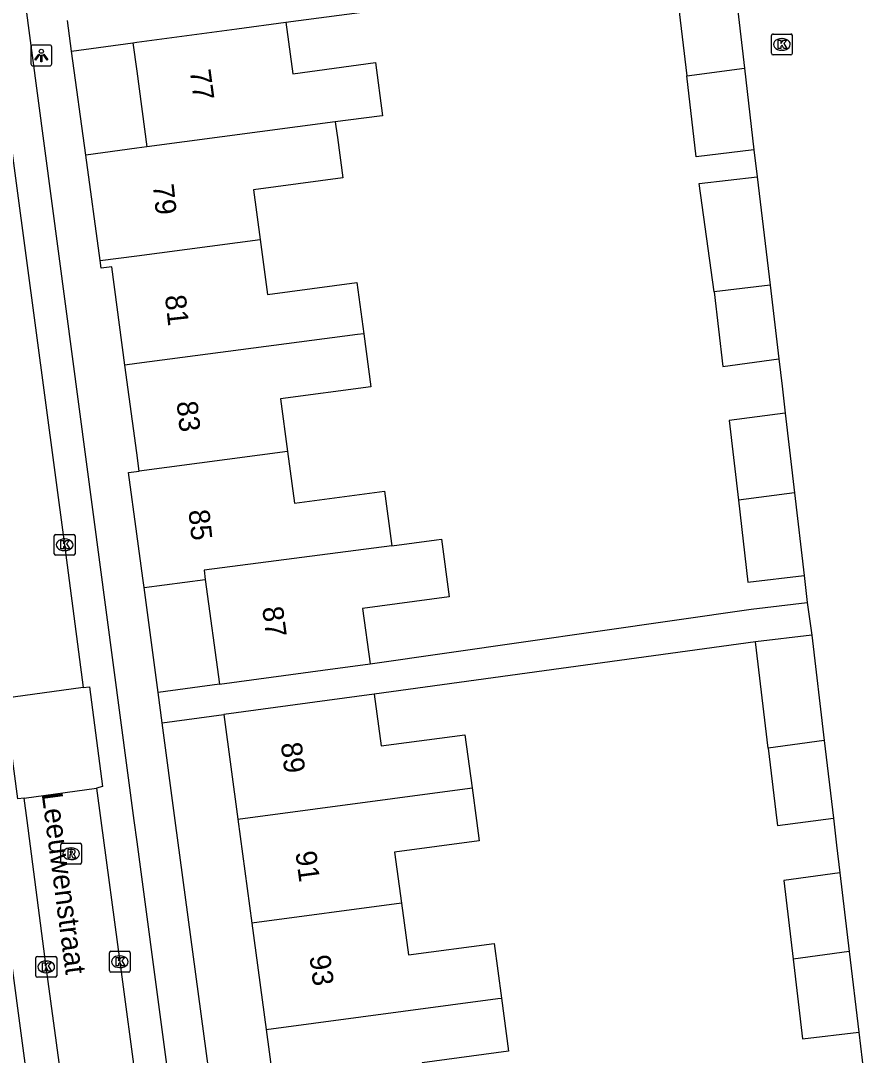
# Model space of a CAD drawing. Extents: x 163150 to 163546, y 380933 to 381635.
# Drawn here: x 163494.43 to 163535.32, y 381238.73 to 381288.37 of the extents above; entities that cross this region are included whole.
import ezdxf

# ---------------------------------------------------------------- set-up
doc = ezdxf.new("R2010")
doc.units = 0
for name, color, linetype in [('IMGEO_Kolk', 7, 'Continuous'), ('IMGEO_Lichtpunt', 7, 'Continuous'), ('IMGEO_Openbare_ruimte_label', 7, 'Continuous'), ('IMGEO_Pand', 7, 'Continuous'), ('IMGEO_Pand_nummerreeks', 7, 'Continuous'), ('IMGEO_Rijbaan_lokaal_open', 7, 'Continuous'), ('IMGEO_Rioolput', 7, 'Continuous'), ('IMGEO_Voetpad_open', 7, 'Continuous')]:
    doc.layers.add(name, color=color, linetype=linetype)

msp = doc.modelspace()

# ---------------------------------------------------------------- linework, layer by layer
at = {"layer": 'IMGEO_Kolk'}
for p, q in [((163530.439, 381286.802), (163530.439, 381287.654)), ((163530.514, 381287.728), (163531.366, 381287.728)), ((163530.927, 381287.508), (163530.952, 381287.508)), ((163531.44, 381287.654), (163531.44, 381286.802)), ((163530.95, 381286.948), (163530.925, 381286.948)), ((163531.366, 381286.728), (163530.514, 381286.728)), ((163496.041, 381262.797), (163496.041, 381263.649)), ((163496.116, 381263.723), (163496.968, 381263.723)), ((163496.529, 381263.503), (163496.554, 381263.503)), ((163497.042, 381263.649), (163497.042, 381262.797)), ((163496.552, 381262.943), (163496.527, 381262.943)), ((163496.968, 381262.723), (163496.116, 381262.723)), ((163498.686, 381242.797), (163498.686, 381243.649)), ((163498.761, 381243.723), (163499.613, 381243.723)), ((163499.687, 381243.649), (163499.687, 381242.797)), ((163495.16, 381242.55), (163495.16, 381243.402)), ((163495.235, 381243.476), (163496.087, 381243.476)), ((163495.648, 381243.256), (163495.673, 381243.256)), ((163496.161, 381243.402), (163496.161, 381242.55)), ((163499.174, 381243.503), (163499.199, 381243.503)), ((163495.671, 381242.696), (163495.646, 381242.696)), ((163499.613, 381242.723), (163498.761, 381242.723)), ((163499.197, 381242.943), (163499.172, 381242.943)), ((163496.087, 381242.476), (163495.235, 381242.476))]:
    msp.add_line(p, q, dxfattribs=at)
for points in [[(163530.439, 381286.802), (163530.439, 381287.654)], [(163530.514, 381287.728), (163531.366, 381287.728)], [(163530.76, 381287.428), (163530.883, 381287.428), (163530.883, 381287.277), (163531.013, 381287.428), (163531.177, 381287.428), (163531.031, 381287.277), (163531.184, 381287.028), (163531.032, 381287.028), (163530.947, 381287.192), (163530.883, 381287.125), (163530.883, 381287.028), (163530.76, 381287.028), (163530.76, 381287.428)], [(163531.44, 381287.654), (163531.44, 381286.802)], [(163531.366, 381286.728), (163530.514, 381286.728)], [(163496.041, 381262.797), (163496.041, 381263.649)], [(163496.116, 381263.723), (163496.968, 381263.723)], [(163497.042, 381263.649), (163497.042, 381262.797)], [(163496.362, 381263.423), (163496.485, 381263.423), (163496.485, 381263.272), (163496.615, 381263.423), (163496.779, 381263.423), (163496.633, 381263.272), (163496.786, 381263.023), (163496.634, 381263.023), (163496.549, 381263.187), (163496.485, 381263.12), (163496.485, 381263.023), (163496.362, 381263.023), (163496.362, 381263.423)], [(163496.968, 381262.723), (163496.116, 381262.723)], [(163498.686, 381242.797), (163498.686, 381243.649)], [(163498.761, 381243.723), (163499.613, 381243.723)], [(163499.687, 381243.649), (163499.687, 381242.797)], [(163495.16, 381242.55), (163495.16, 381243.402)], [(163495.235, 381243.476), (163496.087, 381243.476)], [(163495.481, 381243.176), (163495.604, 381243.176), (163495.604, 381243.025), (163495.734, 381243.176), (163495.898, 381243.176), (163495.752, 381243.025), (163495.905, 381242.776), (163495.753, 381242.776), (163495.668, 381242.94), (163495.604, 381242.873), (163495.604, 381242.776), (163495.481, 381242.776), (163495.481, 381243.176)], [(163496.161, 381243.402), (163496.161, 381242.55)], [(163499.007, 381243.423), (163499.13, 381243.423), (163499.13, 381243.272), (163499.26, 381243.423), (163499.424, 381243.423), (163499.278, 381243.272), (163499.431, 381243.023), (163499.279, 381243.023), (163499.194, 381243.187), (163499.13, 381243.12), (163499.13, 381243.023), (163499.007, 381243.023), (163499.007, 381243.423)], [(163499.613, 381242.723), (163498.761, 381242.723)], [(163496.087, 381242.476), (163495.235, 381242.476)]]:
    msp.add_lwpolyline(points, dxfattribs=at)
for centre, start, end in [((163530.516, 381287.652), 91.552, 178.448), ((163530.516, 381287.652), 91.552, 178.448), ((163531.364, 381287.652), 1.552, 88.448), ((163531.364, 381287.652), 1.552, 88.448), ((163530.516, 381286.804), 181.552, 268.448), ((163530.516, 381286.804), 181.552, 268.448), ((163531.364, 381286.804), 271.552, 358.448), ((163531.364, 381286.804), 271.552, 358.448), ((163496.118, 381263.647), 91.552, 178.448), ((163496.118, 381263.647), 91.552, 178.448), ((163496.966, 381263.647), 1.552, 88.448), ((163496.966, 381263.647), 1.552, 88.448), ((163496.118, 381262.799), 181.552, 268.448), ((163496.118, 381262.799), 181.552, 268.448), ((163496.966, 381262.799), 271.552, 358.448), ((163496.966, 381262.799), 271.552, 358.448), ((163498.763, 381243.647), 91.552, 178.448), ((163498.763, 381243.647), 91.552, 178.448), ((163499.611, 381243.647), 1.552, 88.448), ((163499.611, 381243.647), 1.552, 88.448), ((163495.237, 381243.4), 91.552, 178.448), ((163495.237, 381243.4), 91.552, 178.448), ((163496.085, 381243.4), 1.552, 88.448), ((163496.085, 381243.4), 1.552, 88.448), ((163498.763, 381242.799), 181.552, 268.448), ((163498.763, 381242.799), 181.552, 268.448), ((163499.611, 381242.799), 271.552, 358.448), ((163499.611, 381242.799), 271.552, 358.448), ((163495.237, 381242.552), 181.552, 268.448), ((163495.237, 381242.552), 181.552, 268.448), ((163496.085, 381242.552), 271.552, 358.448), ((163496.085, 381242.552), 271.552, 358.448)]:
    msp.add_arc(centre, 0.0765, start, end, dxfattribs=at)
for centre, major_axis, ratio, start_param, end_param in [((163530.926, 381287.228), (-0.387, 0.002), 0.722429, 4.712389, 7.853982), ((163530.951, 381287.228), (-0.39, 0.002), 0.717154, 1.570796, 4.712389), ((163496.528, 381263.223), (-0.387, 0.002), 0.722429, 4.712389, 7.853982), ((163496.553, 381263.223), (-0.39, 0.002), 0.717154, 1.570796, 4.712389), ((163495.647, 381242.976), (-0.387, 0.002), 0.722429, 4.712389, 7.853982), ((163495.672, 381242.976), (-0.39, 0.002), 0.717154, 1.570796, 4.712389), ((163499.173, 381243.223), (-0.387, 0.002), 0.722429, 4.712389, 7.853982), ((163499.198, 381243.223), (-0.39, 0.002), 0.717154, 1.570796, 4.712389)]:
    msp.add_ellipse(centre, major_axis=major_axis, ratio=ratio, start_param=start_param, end_param=end_param, dxfattribs=at)
at = {"layer": 'IMGEO_Lichtpunt'}
for p, q in [((163494.925, 381287.103), (163494.925, 381286.296)), ((163494.925, 381287.103), (163494.925, 381286.296)), ((163495.827, 381287.198), (163495.019, 381287.198)), ((163495.827, 381287.198), (163495.019, 381287.198)), ((163495.921, 381286.296), (163495.921, 381287.103)), ((163495.921, 381286.296), (163495.921, 381287.103)), ((163495.019, 381286.202), (163495.827, 381286.202)), ((163495.019, 381286.202), (163495.827, 381286.202))]:
    msp.add_line(p, q, dxfattribs=at)
for points in [[(163495.299, 381286.767), (163495.338, 381286.739), (163495.15, 381286.477), (163495.112, 381286.504), (163495.299, 381286.767)], [(163495.511, 381286.739), (163495.549, 381286.766), (163495.736, 381286.504), (163495.697, 381286.476), (163495.511, 381286.739)], [(163495.401, 381286.719), (163495.448, 381286.719), (163495.448, 381286.397), (163495.401, 381286.397), (163495.401, 381286.719)]]:
    msp.add_lwpolyline(points, dxfattribs=at)
msp.add_circle((163495.424, 381286.901), 0.0994, dxfattribs=at)
for centre, start, end in [((163495.019, 381287.103), 90, 180), ((163495.019, 381287.103), 90, 180), ((163495.827, 381287.103), 0, 90), ((163495.827, 381287.103), 0, 90), ((163495.019, 381286.296), 180, 270), ((163495.019, 381286.296), 180, 270), ((163495.827, 381286.296), 270, 0), ((163495.827, 381286.296), 270, 360)]:
    msp.add_arc(centre, 0.0946, start, end, dxfattribs=at)
at = {"layer": 'IMGEO_Pand'}
for points in [[(163528.71, 381289.796), (163525.939, 381289.473), (163526.375, 381285.729)], [(163528.71, 381289.796), (163529.141, 381286.094)], [(163499.816, 381287.309), (163500, 381287.334), (163504.795, 381287.979), (163507.155, 381288.296)], [(163507.155, 381288.296), (163507.488, 381285.823), (163511.447, 381286.355), (163511.791, 381283.807), (163511.644, 381283.788), (163509.523, 381283.509)], [(163499.816, 381287.309), (163500, 381285.942), (163500.488, 381282.318)], [(163526.375, 381285.729), (163529.141, 381286.094)], [(163529.141, 381286.094), (163529.6, 381282.164)], [(163529.6, 381282.164), (163526.829, 381281.841), (163526.375, 381285.729)], [(163509.523, 381283.509), (163500.488, 381282.318)], [(163509.523, 381283.509), (163509.552, 381283.291), (163509.624, 381282.757), (163509.884, 381280.823), (163505.601, 381280.247), (163505.921, 381277.867)], [(163500.488, 381282.318), (163500, 381282.252), (163497.556, 381281.923)], [(163498.238, 381276.858), (163497.556, 381281.923)], [(163527.686, 381275.36), (163526.979, 381280.551), (163529.75, 381280.874)], [(163529.75, 381280.874), (163530.382, 381275.674)], [(163498.238, 381276.858), (163500, 381277.09), (163505.921, 381277.867)], [(163505.921, 381277.867), (163506.276, 381275.229), (163510.556, 381275.805), (163510.887, 381273.347)], [(163499.434, 381271.845), (163498.8, 381276.56), (163498.287, 381276.491), (163498.238, 381276.858)], [(163530.382, 381275.674), (163527.686, 381275.36)], [(163527.686, 381275.36), (163528.104, 381271.782), (163530.795, 381272.139)], [(163530.382, 381275.674), (163530.795, 381272.139)], [(163510.887, 381273.347), (163510.579, 381273.307), (163500, 381271.919), (163499.434, 381271.845)], [(163510.887, 381273.347), (163511.229, 381270.804), (163506.897, 381270.222), (163507.236, 381267.699)], [(163500.119, 381266.756), (163500, 381267.641), (163499.434, 381271.845)], [(163531.098, 381269.542), (163528.406, 381269.185), (163528.852, 381265.361)], [(163531.098, 381269.542), (163531.544, 381265.714)], [(163507.236, 381267.699), (163500.119, 381266.756)], [(163507.236, 381267.699), (163507.569, 381265.224), (163511.874, 381265.803), (163512.212, 381263.288), (163512.226, 381263.181)], [(163500.348, 381261.17), (163500.288, 381261.616), (163500, 381263.757), (163499.606, 381266.687), (163500.119, 381266.756)], [(163531.544, 381265.714), (163528.852, 381265.361)], [(163531.544, 381265.714), (163532.006, 381261.75)], [(163528.852, 381265.361), (163529.31, 381261.436), (163532.006, 381261.75)], [(163512.226, 381263.181), (163514.374, 381263.463), (163514.609, 381263.494), (163514.981, 381260.734), (163510.829, 381260.175), (163511.187, 381257.513)], [(163512.226, 381263.181), (163503.227, 381262.001), (163503.286, 381261.566)], [(163500.348, 381261.17), (163503.286, 381261.566)], [(163503.286, 381261.566), (163503.962, 381256.541)], [(163532.376, 381258.889), (163529.68, 381258.575)], [(163530.283, 381253.469), (163529.68, 381258.575)], [(163532.376, 381258.889), (163532.973, 381253.829)], [(163503.962, 381256.541), (163508.918, 381257.208), (163511.187, 381257.513)], [(163511.38, 381256.054), (163509.13, 381255.751), (163504.174, 381255.085)], [(163511.38, 381256.054), (163511.714, 381253.572), (163515.739, 381254.113), (163516.081, 381251.569)], [(163504.174, 381255.085), (163504.849, 381250.067)], [(163532.973, 381253.829), (163530.283, 381253.469)], [(163532.973, 381253.829), (163533.411, 381250.117)], [(163530.283, 381253.469), (163530.692, 381250), (163530.721, 381249.757), (163533.411, 381250.117)], [(163504.849, 381250.067), (163515.966, 381251.554), (163516.081, 381251.569)], [(163516.081, 381251.569), (163516.292, 381250), (163516.423, 381249.026), (163512.367, 381248.481), (163512.697, 381246.027)], [(163504.849, 381250.067), (163505.522, 381245.067)], [(163533.722, 381247.486), (163531.031, 381247.126), (163531.477, 381243.35)], [(163533.722, 381247.486), (163534.168, 381243.71)], [(163512.697, 381246.027), (163505.522, 381245.067)], [(163512.697, 381246.027), (163513.03, 381243.549), (163517.135, 381244.101), (163517.488, 381241.478)], [(163505.522, 381245.067), (163506.207, 381239.968)], [(163534.168, 381243.71), (163531.477, 381243.35)], [(163534.168, 381243.71), (163534.624, 381239.844)], [(163531.477, 381243.35), (163531.928, 381239.53), (163534.624, 381239.844)], [(163506.207, 381239.968), (163517.317, 381241.455), (163517.488, 381241.478)], [(163517.488, 381241.478), (163517.83, 381238.933), (163513.69, 381238.376), (163514.021, 381235.914)], [(163506.207, 381239.968), (163506.881, 381234.959)]]:
    msp.add_lwpolyline(points, dxfattribs=at)
at = {"layer": 'IMGEO_Rijbaan_lokaal_open'}
for points in [[(163490.402, 381309.443), (163490.846, 381305.849), (163493.759, 381284.035), (163496.541, 381263.222), (163497.43, 381256.373)], [(163529.6, 381282.164), (163529.75, 381280.874)], [(163530.795, 381272.139), (163530.946, 381270.841), (163531.098, 381269.542)], [(163532.006, 381261.75), (163532.157, 381260.455)], [(163532.157, 381260.455), (163532.376, 381258.889)], [(163497.43, 381256.373), (163494.08, 381255.92)], [(163497.43, 381256.373), (163497.739, 381256.415), (163498.362, 381251.625), (163498.069, 381251.55)], [(163494.609, 381251.077), (163494.305, 381251.042), (163493.658, 381255.873), (163494.08, 381255.92)], [(163494.609, 381251.077), (163498.069, 381251.55)], [(163498.069, 381251.55), (163498.277, 381250), (163499.186, 381243.223), (163500, 381237.114), (163502.031, 381221.873), (163503.782, 381208.782)], [(163503.549, 381184.23), (163501.36, 381200.568), (163500, 381210.764), (163498.574, 381221.455), (163495.662, 381242.977), (163494.749, 381250), (163494.609, 381251.077)], [(163533.411, 381250.117), (163533.564, 381248.819), (163533.722, 381247.486)], [(163534.624, 381239.844), (163534.783, 381238.501), (163535.323, 381233.486)]]:
    msp.add_lwpolyline(points, dxfattribs=at)
at = {"layer": 'IMGEO_Rioolput'}
for p, q in [((163496.352, 381247.979), (163496.352, 381248.831)), ((163496.427, 381248.905), (163497.279, 381248.905)), ((163496.84, 381248.685), (163496.865, 381248.685)), ((163497.353, 381248.831), (163497.353, 381247.979)), ((163496.863, 381248.125), (163496.838, 381248.125)), ((163497.279, 381247.905), (163496.427, 381247.905))]:
    msp.add_line(p, q, dxfattribs=at)
for points in [[(163496.352, 381247.979), (163496.352, 381248.831)], [(163496.427, 381248.905), (163497.279, 381248.905)], [(163496.941, 381248.603), (163496.689, 381248.605), (163496.689, 381248.205)], [(163497.353, 381248.831), (163497.353, 381247.979)], [(163496.689, 381248.205), (163496.813, 381248.205), (163496.813, 381248.367), (163496.824, 381248.367)], [(163496.867, 381248.524), (163496.813, 381248.524), (163496.813, 381248.443)], [(163496.813, 381248.443), (163496.865, 381248.443)], [(163496.871, 381248.338), (163496.942, 381248.205), (163497.082, 381248.205), (163497.017, 381248.331)], [(163497.279, 381247.905), (163496.427, 381247.905)]]:
    msp.add_lwpolyline(points, dxfattribs=at)
for centre, radius, start, end in [((163496.429, 381248.829), 0.0765, 91.552, 178.448), ((163496.429, 381248.829), 0.0765, 91.552, 178.448), ((163496.94, 381248.493), 0.109, 350.3612, 89.416), ((163497.277, 381248.829), 0.0765, 1.552, 88.448), ((163497.277, 381248.829), 0.0765, 1.552, 88.448), ((163496.823, 381248.314), 0.0533, 26.0293, 88.6989), ((163496.849, 381248.632), 0.19, 274.7715, 282.9687), ((163496.873, 381248.428), 0.0964, 77.0061, 93.1865), ((163496.887, 381248.485), 0.0378, 276.6634, 79.6772), ((163496.938, 381248.493), 0.112, 277.5842, 350.9817), ((163496.922, 381248.278), 0.108, 29.5134, 73.7905), ((163496.429, 381247.981), 0.0765, 181.552, 268.448), ((163496.429, 381247.981), 0.0765, 181.552, 268.448), ((163497.277, 381247.981), 0.0765, 271.552, 358.448), ((163497.277, 381247.981), 0.0765, 271.552, 358.448)]:
    msp.add_arc(centre, radius, start, end, dxfattribs=at)
for centre, major_axis, ratio, start_param, end_param in [((163496.839, 381248.405), (-0.387, 0.002), 0.722429, 4.712389, 7.853982), ((163496.864, 381248.405), (-0.39, 0.002), 0.717154, 1.570796, 4.712389)]:
    msp.add_ellipse(centre, major_axis=major_axis, ratio=ratio, start_param=start_param, end_param=end_param, dxfattribs=at)
at = {"layer": 'IMGEO_Voetpad_open'}
for points in [[(163492.278, 381306.923), (163499.864, 381250), (163500, 381248.982), (163504.96, 381211.766)], [(163507.155, 381288.296), (163525.788, 381290.766), (163528.559, 381291.089)], [(163496.878, 381286.909), (163496.679, 381288.37)], [(163496.878, 381286.909), (163499.816, 381287.309)], [(163497.556, 381281.923), (163496.878, 381286.909)], [(163488.802, 381281.887), (163493.061, 381250), (163500, 381198.044), (163501.78, 381184.716), (163502.086, 381184.001), (163503.191, 381183.057), (163503.412, 381182.858)], [(163501.023, 381256.146), (163500.348, 381261.17)], [(163511.187, 381257.513), (163529.461, 381260.141), (163532.157, 381260.455)], [(163529.68, 381258.575), (163511.38, 381256.054)], [(163503.962, 381256.541), (163501.023, 381256.146)], [(163501.219, 381254.688), (163501.023, 381256.146)], [(163501.219, 381254.688), (163504.174, 381255.085)], [(163505.332, 381224.08), (163501.849, 381250), (163501.219, 381254.688)]]:
    msp.add_lwpolyline(points, dxfattribs=at)

# ---------------------------------------------------------------- texts
at = {"layer": 'IMGEO_Openbare_ruimte_label'}
msp.add_text('Leeuwenstraat', height=1, rotation=277.5871, dxfattribs=at).set_placement((163495.44, 381251.266))
at = {"layer": 'IMGEO_Pand_nummerreeks'}
for s, rotation, p in [('77', 277.666, (163502.539, 381285.968)), ('79', 276.245, (163500.769, 381280.485)), ('81', 276.2458, (163501.352, 381275.167)), ('83', 276.2458, (163501.909, 381270.074)), ('85', 276.245, (163502.478, 381264.868)), ('87', 277.6602, (163506.011, 381260.208)), ('89', 277.661, (163506.904, 381253.689)), ('91', 277.661, (163507.605, 381248.476)), ('93', 277.661, (163508.277, 381243.487))]:
    msp.add_text(s, height=1, rotation=rotation, dxfattribs=at).set_placement(p)

doc.saveas('drawing.dxf')
